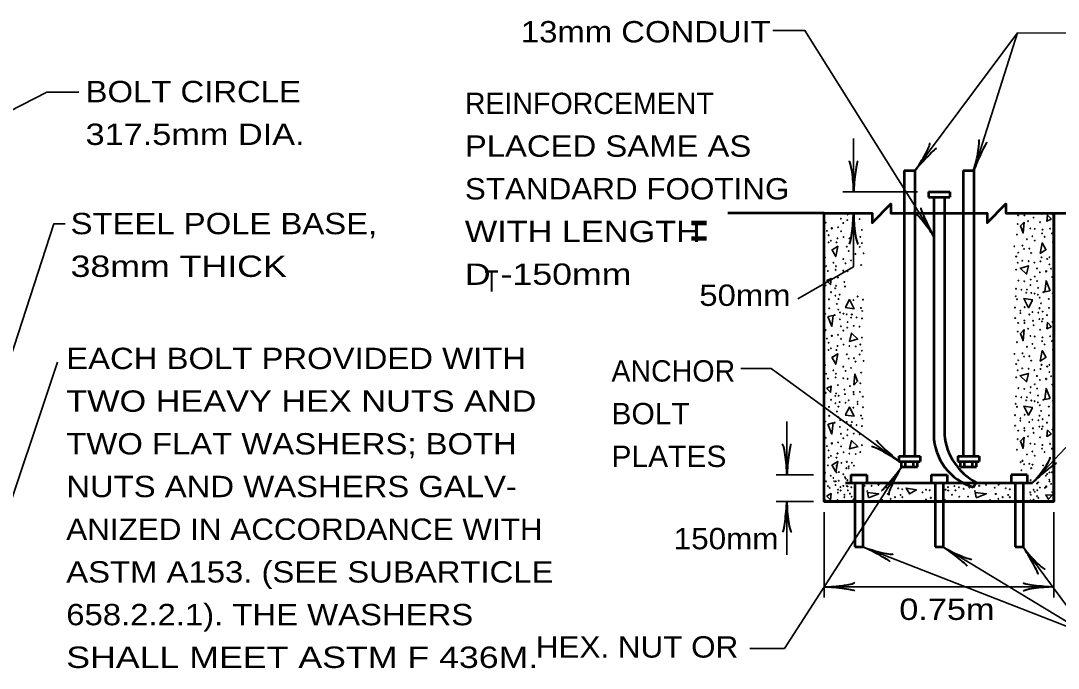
# Model space of a CAD drawing. Extents: x -35 to 821, y -13 to 531.
# Drawn here: x 339.2 to 455.8, y 171.6 to 244.4 of the extents above; entities that cross this region are included whole.
import ezdxf

# ---------------------------------------------------------------- set-up
doc = ezdxf.new("R2010")
doc.units = 0
doc.header["$LTSCALE"] = 0.96
doc.layers.add('1', color=7, linetype='Continuous', lineweight=53)

msp = doc.modelspace()

# ---------------------------------------------------------------- linework, layer by layer
at = {"layer": '1', "lineweight": 35}
for p, q in [((439.7334, 227.5357), (451.256, 243.0208)), ((342.1524, 236.3488), (311.1905, 220.4616)), ((342.1524, 236.3488), (345.7524, 236.3488)), ((432.8334, 225.1357), (432.8334, 231.1357)), ((440.0334, 225.1357), (431.6334, 225.1357)), ((432.8334, 222.7356), (432.8334, 216.7356)), ((432.8334, 216.7356), (426.5646, 213.1228)), ((333.7347, 177.2878), (343.3335, 205.9941)), ((425.3334, 193.3357), (425.3334, 199.3357)), ((438.2334, 194.2357), (425.0803, 173.8214)), ((428.3334, 193.3357), (424.1334, 193.3357)), ((428.3334, 190.3357), (424.1334, 190.3357)), ((425.3334, 190.3357), (425.3334, 184.3357)), ((429.5334, 189.1357), (429.5334, 179.5357)), ((455.3334, 189.1357), (455.3334, 179.5357)), ((433.8834, 185.2357), (459.1446, 175.3797)), ((442.8834, 185.2357), (459.1446, 175.3797)), ((451.8834, 185.2357), (459.1446, 175.3797)), ((429.5334, 180.7357), (455.3334, 180.7357)), ((425.0803, 173.8214), (421.1616, 173.8214))]:
    msp.add_line(p, q, dxfattribs=at)
at = {"layer": '1'}
for p, q in [((438.5334, 227.5357), (438.5334, 195.4357)), ((438.5334, 227.5357), (439.7334, 227.5357)), ((439.7334, 227.5357), (439.7334, 195.4357)), ((445.1334, 227.5357), (445.1334, 195.4357)), ((445.1334, 227.5357), (446.3334, 227.5357)), ((446.3334, 227.5357), (446.3334, 195.4357)), ((441.2334, 225.1357), (443.6334, 225.1357)), ((441.2334, 225.1357), (441.2334, 224.5357)), ((443.6334, 225.1357), (443.6334, 224.5357)), ((441.2334, 224.5357), (443.6334, 224.5357)), ((441.8334, 224.5357), (441.8334, 197.8357)), ((443.0334, 224.5357), (443.0334, 197.8357)), ((429.5334, 222.7356), (418.7121, 222.7356)), ((429.5334, 190.3357), (429.5334, 222.7356)), ((455.3334, 222.7358), (464.9547, 222.7358)), ((455.3334, 190.3357), (455.3334, 222.7358)), ((437.9334, 195.4357), (440.3334, 195.4357)), ((437.9334, 195.4357), (437.9334, 194.8357)), ((437.9334, 194.8357), (440.3334, 194.8357)), ((438.2334, 194.2357), (438.2334, 194.8357)), ((438.6834, 194.2357), (438.6834, 194.8357)), ((439.5834, 194.2357), (439.5834, 194.8357)), ((440.0334, 194.2357), (440.0334, 194.8357)), ((440.3334, 195.4357), (440.3334, 194.8357)), ((444.5334, 195.4357), (446.9334, 195.4357)), ((444.5334, 195.4357), (444.5334, 194.8357)), ((444.5334, 194.8357), (446.9334, 194.8357)), ((444.8334, 194.2357), (444.8334, 194.8357)), ((445.2834, 194.2357), (445.2834, 194.8357)), ((446.1834, 194.2357), (446.1834, 194.8357)), ((446.6334, 194.2357), (446.6334, 194.8357)), ((446.9334, 195.4357), (446.9334, 194.8357)), ((438.2334, 194.2357), (440.0334, 194.2357)), ((444.8334, 194.2357), (446.6334, 194.2357)), ((431.9334, 192.4357), (452.9334, 192.4357)), ((432.5334, 193.3357), (432.5334, 192.4357)), ((432.5334, 193.3357), (434.3334, 193.3357)), ((432.9834, 192.4357), (432.9834, 185.2357)), ((433.8834, 192.4357), (433.8834, 185.2357)), ((434.3334, 193.3357), (434.3334, 192.4357)), ((441.5334, 193.3357), (441.5334, 192.4357)), ((441.5334, 193.3357), (443.3334, 193.3357)), ((441.9834, 192.4357), (441.9834, 185.2357)), ((442.8834, 192.4357), (442.8834, 185.2357)), ((443.3334, 193.3357), (443.3334, 192.4357)), ((446.6076, 192.4697), (446.2673, 191.8959)), ((450.5334, 193.3357), (450.5334, 192.4357)), ((452.3334, 193.3357), (450.5334, 193.3357)), ((450.9834, 192.4357), (450.9834, 185.2357)), ((451.8834, 192.4357), (451.8834, 185.2357)), ((452.3334, 193.3357), (452.3334, 192.4357)), ((429.5334, 190.3357), (455.3334, 190.3357)), ((432.9834, 185.2357), (433.8834, 185.2357)), ((441.9834, 185.2357), (442.8834, 185.2357)), ((450.9834, 185.2357), (451.8834, 185.2357))]:
    msp.add_line(p, q, dxfattribs=at)
at = {"layer": '1', "lineweight": 35}
for points in [[(441.8334, 220.1625), (427.3681, 243.2875), (423.7562, 243.2875)], [(446.3334, 227.5357), (451.256, 243.0208), (456.9977, 243.0019)], [(455.0934, 222.0878), (454.6134, 222.5438), (454.5654, 221.8478), (455.0454, 222.0878)], [(326.909, 172.1878), (342.9245, 221.5527), (344.2093, 221.5527)], [(454.4694, 218.6078), (454.0374, 219.3998), (453.8214, 218.2238), (454.4934, 218.6558)], [(430.3974, 218.6557), (430.8294, 217.8637), (431.0454, 219.0397), (430.3734, 218.6077)], [(451.5174, 216.5438), (452.4774, 216.8318), (452.2854, 215.8958), (451.5654, 216.5678)], [(429.7734, 215.1757), (430.2534, 214.7197), (430.3014, 215.4157), (429.8214, 215.1757)], [(454.9254, 214.0238), (454.4694, 215.1518), (454.3254, 213.9038), (454.8774, 214.0238)], [(431.9094, 212.1997), (432.3894, 213.0397), (432.8934, 212.0077), (431.8854, 212.1517)], [(452.9574, 212.9678), (452.4774, 212.1278), (451.9734, 213.1598), (452.9814, 213.0158)], [(429.9414, 211.1437), (430.3974, 210.0157), (430.5414, 211.2637), (429.9894, 211.1437)], [(455.0934, 209.9918), (454.6134, 210.4478), (454.5654, 209.7518), (455.0454, 209.9918)], [(433.3494, 208.6237), (432.3894, 208.3357), (432.5814, 209.2717), (433.3014, 208.5997)], [(430.3974, 206.5597), (430.8294, 205.7677), (431.0454, 206.9437), (430.3734, 206.5117)], [(454.4694, 206.5118), (454.0374, 207.3038), (453.8214, 206.1278), (454.4934, 206.5598)], [(437.9334, 194.8357), (423.5538, 205.2899), (420.1719, 205.2899)], [(452.9334, 192.4357), (465.3716, 205.6121), (469.2367, 205.6121)], [(451.5174, 204.4478), (452.4774, 204.7358), (452.2854, 203.7998), (451.5654, 204.4718)], [(429.7734, 203.0797), (430.2534, 202.6237), (430.3014, 203.3197), (429.8214, 203.0797)], [(454.9254, 201.9278), (454.4694, 203.0558), (454.3254, 201.8078), (454.8774, 201.9278)], [(431.9094, 200.1037), (432.3894, 200.9437), (432.8934, 199.9117), (431.8854, 200.0557)], [(452.9574, 200.8718), (452.4774, 200.0318), (451.9734, 201.0638), (452.9814, 200.9198)], [(429.9414, 199.0477), (430.3974, 197.9197), (430.5414, 199.1677), (429.9894, 199.0477)], [(455.0934, 197.8958), (454.6134, 198.3518), (454.5654, 197.6558), (455.0454, 197.8958)], [(433.3494, 196.5277), (432.3894, 196.2397), (432.5814, 197.1757), (433.3014, 196.5037)], [(430.3974, 194.4637), (430.8294, 193.6717), (431.0454, 194.8477), (430.3734, 194.4157)], [(434.5254, 190.7437), (435.6534, 191.1997), (434.4054, 191.3437), (434.5254, 190.7917)], [(439.1094, 191.1997), (439.9014, 191.6317), (438.7254, 191.8477), (439.1574, 191.1757)], [(446.6214, 190.7437), (447.7494, 191.1997), (446.5014, 191.3437), (446.6214, 190.7917)], [(429.7734, 190.9837), (430.2534, 190.5277), (430.3014, 191.2237), (429.8214, 190.9837)], [(454.6854, 190.5757), (455.1414, 191.0557), (454.4454, 191.1037), (454.6854, 190.6237)]]:
    msp.add_lwpolyline(points, dxfattribs=at)
at = {"layer": '1'}
msp.add_lwpolyline([(429.5334, 222.7356), (434.9121, 222.7356), (434.9121, 221.675), (437.0334, 223.7963), (437.0334, 222.7357), (447.8334, 222.7357), (447.8334, 221.6751), (449.9547, 223.7964), (449.9547, 222.7358), (455.3334, 222.7358), (455.3334, 190.3357), (429.5334, 190.3357)], close=True, dxfattribs=at)
at = {"layer": '1', "lineweight": 35}
for points in [[(452.0214, 221.7518), (451.8774, 220.5038), (451.5894, 221.3198)], [(452.0214, 209.6558), (451.8774, 208.4078), (451.5894, 209.2238)], [(432.8454, 203.4157), (432.9894, 204.6637), (433.2774, 203.8477)], [(452.0214, 197.5598), (451.8774, 196.3118), (451.5894, 197.1278)]]:
    msp.add_lwpolyline(points, close=True, dxfattribs=at)
for centre in [(429.7048, 221.6917), (431.407, 222.1371), (431.6774, 221.6441), (432.1229, 221.978), (432.1547, 222.5982), (433.5069, 222.0894), (451.328, 222.5058), (452.044, 222.5058), (452.4416, 221.8537), (453.0621, 222.2514), (453.7939, 221.7424), (454.0007, 222.6807), (455.178, 222.6171), (429.832, 220.7535), (430.3888, 221.0874), (430.3888, 221.0238), (431.0888, 221.167), (431.4229, 220.7216), (433.7616, 220.8648), (451.2803, 221.5356), (452.7121, 221.0426), (453.1894, 220.9791), (454.0166, 220.47), (454.0643, 220.8836), (454.9234, 221.0108), (455.1302, 220.47), (430.0229, 220.2763), (430.0229, 219.4652), (430.2775, 219.6561), (430.9139, 219.4653), (431.0251, 219.9264), (431.7093, 220.0696), (432.3615, 219.9105), (433.5865, 220.0855), (433.7616, 219.3857), (451.1849, 220.3428), (452.3143, 219.8181), (452.9349, 220.152), (453.1894, 219.6749), (454.303, 220.0884), (455.2416, 219.4999), (429.5457, 218.7177), (432.0752, 218.9881), (432.282, 218.4951), (433.0456, 218.1611), (433.5229, 218.9563), (433.9524, 218.2407), (450.9144, 219.0228), (451.3439, 218.3072), (451.8212, 219.1024), (451.9962, 218.7206), (452.5848, 218.7684), (452.7916, 218.2754), (455.3211, 218.5458), (429.6252, 217.7636), (430.5638, 217.1751), (431.6774, 217.5886), (431.9319, 217.1115), (432.5525, 217.4454), (433.6819, 216.9207), (451.1052, 217.8778), (451.2803, 217.178), (451.7894, 217.4007), (452.5053, 217.353), (453.1575, 217.1939), (453.8417, 217.3371), (453.9529, 217.7982), (454.5893, 217.6074), (454.8439, 217.7983), (454.8439, 216.9872), (429.7366, 216.7935), (429.9434, 216.2527), (430.8025, 216.3799), (430.8502, 216.7935), (431.6774, 216.2844), (432.1547, 216.2209), (451.1052, 216.3987), (453.4439, 216.5419), (453.778, 216.0965), (454.478, 216.2397), (454.478, 216.1761), (455.0348, 216.51), (429.6888, 214.6464), (430.8661, 214.5828), (431.0729, 215.5211), (431.8047, 215.0121), (451.3599, 215.1741), (452.0121, 215.0947), (452.7121, 214.6653), (452.7439, 215.2855), (453.1894, 215.6194), (453.4598, 215.1264), (455.162, 215.5718), (429.4662, 213.6194), (430.2933, 213.8739), (430.7706, 214.3033), (430.7865, 213.4762), (431.2638, 213.6036), (431.8683, 214.51), (451.0576, 213.4088), (451.0894, 214.2517), (451.6939, 214.1404), (452.2348, 213.8064), (452.3143, 214.1563), (452.8076, 213.7905), (453.1735, 213.711), (453.5553, 213.5838), (453.5712, 214.3471), (454.1598, 213.8701), (455.2256, 213.7428), (455.2734, 214.5062), (429.5298, 213.0151), (430.0707, 213.0628), (430.9615, 212.5538), (431.1365, 213.0946), (432.807, 212.9832), (433.2843, 213.3809), (433.8888, 213.031), (451.2007, 213.0748), (453.762, 213.2498), (453.9053, 212.6137), (454.7802, 213.1067), (429.6412, 211.4247), (430.0866, 212.0608), (430.707, 211.2974), (431.1048, 211.9177), (431.3115, 211.5837), (431.6933, 211.4565), (432.0592, 211.377), (432.632, 211.3611), (433.6661, 212.0927), (433.8092, 211.7587), (450.978, 212.1365), (451.5825, 211.7866), (451.5825, 211.5163), (452.0598, 212.1843), (452.5848, 211.3572), (452.9349, 211.6277), (453.603, 211.5639), (453.7303, 212.0729), (454.0803, 211.6913), (454.5735, 211.2936), (454.7961, 212.1047), (455.337, 212.1524), (455.4006, 211.5481), (429.5934, 210.6613), (431.2956, 210.8204), (431.407, 210.0411), (432.1547, 210.5022), (432.5525, 211.0112), (432.8547, 210.0728), (433.1729, 211.0271), (433.5069, 209.9934), (433.7774, 210.9158), (450.994, 210.9597), (451.328, 210.4098), (452.0253, 210.6811), (452.044, 210.4098), (452.9985, 210.6575), (453.0621, 210.1554), (453.7144, 210.8484), (454.0007, 210.5847), (454.0962, 210.8642), (455.178, 210.5211), (429.7048, 209.5957), (430.3888, 208.9914), (430.3888, 208.9278), (431.0888, 209.071), (431.6774, 209.5481), (432.1229, 209.882), (433.7616, 208.7688), (451.2803, 209.4396), (452.4416, 209.7577), (452.7121, 208.9466), (453.1894, 208.8831), (453.7939, 209.6464), (454.0643, 208.7876), (454.9234, 208.9148), (429.832, 208.6575), (430.0229, 208.1803), (430.2775, 207.5601), (431.0251, 207.8304), (431.4229, 208.6256), (431.7093, 207.9736), (432.3615, 207.8145), (433.0774, 207.7668), (433.5865, 207.9895), (451.1849, 208.2468), (452.3143, 207.7221), (452.9349, 208.056), (453.1894, 207.5789), (454.0166, 208.374), (454.303, 207.9924), (455.1302, 208.374), (429.5457, 206.6217), (430.0229, 207.3692), (430.9139, 207.3693), (432.0752, 206.8921), (432.282, 206.3991), (432.8706, 206.4469), (433.5229, 206.8603), (433.7616, 207.2897), (450.9144, 206.9268), (451.8212, 207.0064), (451.9962, 206.6246), (452.5848, 206.6724), (455.2416, 207.4039), (455.3211, 206.4498), (429.6252, 205.6676), (431.6774, 205.4926), (432.5525, 205.3494), (433.0456, 206.0651), (433.9524, 206.1447), (451.1052, 205.7818), (451.3439, 206.2112), (451.7894, 205.3047), (452.5053, 205.257), (452.7916, 206.1794), (453.8417, 205.2411), (453.9529, 205.7022), (454.5893, 205.5114), (454.8439, 205.7023), (429.7366, 204.6975), (429.9434, 204.1567), (430.5638, 205.0791), (430.8025, 204.2839), (430.8502, 204.6975), (431.6774, 204.1884), (431.9319, 205.0155), (432.1547, 204.1249), (433.6819, 204.8247), (451.1052, 204.3027), (451.2803, 205.082), (453.1575, 205.0979), (453.4439, 204.4459), (454.478, 204.1437), (454.478, 204.0801), (454.8439, 204.8912), (455.0348, 204.414), (431.0729, 203.4251), (431.8047, 202.9161), (432.4252, 203.3138), (433.5865, 203.6319), (451.3599, 203.0781), (452.0121, 202.9987), (452.7439, 203.1895), (453.1894, 203.5234), (453.4598, 203.0304), (453.778, 204.0005), (455.162, 203.4758), (429.6888, 202.5504), (430.2933, 201.7779), (430.7706, 202.2073), (430.8661, 202.4868), (431.1524, 202.2231), (431.8683, 202.414), (432.8228, 202.6617), (432.8415, 202.3904), (433.5388, 202.6617), (433.8728, 202.1118), (451.0894, 202.1557), (451.6939, 202.0444), (452.3143, 202.0603), (452.7121, 202.5693), (453.5712, 202.2511), (454.1598, 201.7741), (455.2734, 202.4102), (429.4662, 201.5234), (429.5298, 200.9191), (430.0707, 200.9668), (430.7865, 201.3802), (431.1365, 200.9986), (431.2638, 201.5076), (431.9319, 201.4438), (432.282, 201.7143), (432.807, 200.8872), (433.2843, 201.5552), (433.2843, 201.2849), (433.8888, 200.935), (451.0576, 201.3128), (451.2007, 200.9788), (452.2348, 201.7104), (452.8076, 201.6945), (453.1735, 201.615), (453.5553, 201.4878), (453.762, 201.1538), (454.7802, 201.0107), (455.2256, 201.6468), (430.0866, 199.9648), (430.9615, 200.4578), (431.1048, 199.8217), (431.3115, 199.4877), (433.6661, 199.9967), (433.8092, 199.6627), (450.978, 200.0405), (451.5825, 199.6906), (451.5825, 199.4203), (452.0598, 200.0883), (452.9349, 199.5317), (453.603, 199.4679), (453.7303, 199.9769), (453.9053, 200.5177), (454.0803, 199.5953), (454.7961, 200.0087), (455.337, 200.0564), (455.4006, 199.4521), (429.5934, 198.5653), (429.6412, 199.3287), (430.707, 199.2014), (431.2956, 198.7244), (431.6933, 199.3605), (432.0592, 199.281), (432.1547, 198.4062), (432.5525, 198.9152), (432.632, 199.2651), (433.1729, 198.9311), (433.7774, 198.8198), (450.994, 198.8637), (451.328, 198.3138), (452.0253, 198.5851), (452.044, 198.3138), (452.5848, 199.2612), (452.9985, 198.5615), (453.7144, 198.7524), (454.0007, 198.4887), (454.0962, 198.7682), (454.5735, 199.1976), (455.178, 198.4251), (429.7048, 197.4997), (431.407, 197.9451), (431.6774, 197.4521), (432.1229, 197.786), (432.8547, 197.9768), (433.5069, 197.8974), (451.2803, 197.3436), (452.4416, 197.6617), (453.0621, 198.0594), (453.7939, 197.5504), (429.832, 196.5615), (430.0229, 196.0843), (430.3888, 196.8954), (430.3888, 196.8318), (431.0888, 196.975), (431.4229, 196.5296), (433.5865, 195.8935), (433.7616, 196.6728), (451.1849, 196.1508), (452.7121, 196.8506), (452.9349, 195.96), (453.1894, 196.7871), (454.0166, 196.278), (454.0643, 196.6916), (454.303, 195.8964), (454.9234, 196.8188), (455.1302, 196.278), (430.0229, 195.2732), (430.2775, 195.4641), (430.9139, 195.2733), (431.0251, 195.7344), (431.7093, 195.8776), (432.0752, 194.7961), (432.3615, 195.7185), (433.0774, 195.6708), (451.6204, 194.7547), (451.8212, 194.9104), (452.3143, 195.6261), (453.1894, 195.4829), (429.5457, 194.5257), (429.6252, 193.5716), (429.9412, 194.3888), (430.9114, 194.3411), (430.9114, 193.6251), (431.1827, 193.6438), (431.4613, 194.6751), (432.0179, 194.0866), (432.282, 194.3031), (432.2882, 194.0866), (432.6381, 194.6911), (432.8706, 194.3509), (443.0074, 194.3411), (451.7, 193.8479), (451.9962, 194.5286), (452.5848, 194.5764), (452.7916, 194.0834), (452.9404, 194.4842), (454.1332, 194.3888), (454.8439, 193.6063), (455.1034, 193.6251), (429.7366, 192.6015), (430.2593, 193.2275), (430.5638, 192.9831), (430.657, 192.607), (430.8502, 192.6015), (431.1591, 192.6706), (431.6774, 193.3966), (431.8588, 193.0843), (431.9319, 192.9195), (432.1293, 192.7342), (452.7496, 192.7342), (453.5767, 192.4797), (454.4513, 193.2275), (454.5893, 193.4154), (454.8439, 192.7952), (454.849, 192.607), (429.9434, 192.0607), (430.148, 191.8752), (430.8025, 192.1879), (431.0729, 191.3291), (431.0863, 191.6684), (431.35, 191.9547), (431.3658, 191.5729), (431.6774, 192.0924), (432.0655, 192.0661), (432.1547, 192.0289), (432.1929, 191.5888), (432.5745, 191.9388), (434.0854, 192.1138), (434.3717, 191.5093), (434.8487, 192.0979), (435.628, 192.2093), (436.5981, 191.8911), (437.0435, 192.2252), (437.8387, 191.8274), (438.2998, 191.7162), (440.59, 191.3661), (440.9716, 191.6525), (441.3852, 191.6048), (443.1823, 191.6684), (443.446, 191.9547), (443.4618, 191.5729), (444.1615, 192.0661), (444.2889, 191.5888), (444.6705, 191.9388), (445.2113, 191.7638), (445.8474, 191.9071), (446.4677, 191.5093), (446.9447, 192.0979), (447.724, 192.2093), (448.6941, 191.8911), (449.1395, 192.2252), (449.9347, 191.8274), (450.3958, 191.7162), (452.686, 191.3661), (453.0676, 191.6525), (453.1894, 191.4274), (453.4439, 192.3499), (453.4812, 191.6048), (453.778, 191.9045), (454.34, 191.8752), (454.478, 192.0477), (454.478, 191.9841), (455.0348, 192.318), (455.162, 191.3798), (455.2783, 191.6684), (429.6888, 190.4544), (430.8661, 190.3908), (431.0227, 190.4911), (431.7952, 191.0956), (431.8047, 190.8201), (432.4252, 191.2178), (432.6063, 190.873), (432.8228, 190.5657), (436.0734, 190.5071), (436.6777, 191.1911), (436.7413, 191.1911), (437.0116, 190.6343), (437.4888, 190.8252), (438.109, 191.0798), (438.2999, 190.8252), (440.9716, 190.5389), (441.5124, 190.7457), (443.1187, 190.4911), (443.8912, 191.0956), (444.7023, 190.873), (445.7043, 190.8889), (448.1694, 190.5071), (448.7737, 191.1911), (448.8373, 191.1911), (449.1076, 190.6343), (449.5848, 190.8252), (450.205, 191.0798), (450.3959, 190.8252), (452.7121, 190.4733), (452.7439, 191.0935), (453.0676, 190.5389), (453.4598, 190.9344), (453.6084, 190.7457)]:
    msp.add_circle(centre, 0.0318, dxfattribs=at)
at = {"layer": '1'}
for centre, radius, start, end in [((448.1288, 197.9708), 6.2969, 181.22976, 252.89151), ((449.8331, 198.4914), 6.8312, 185.50839, 241.8245)]:
    msp.add_arc(centre, radius, start, end, dxfattribs=at)
at = {"layer": '1', "lineweight": 40}
for centre, major_axis, ratio, start_param, end_param in [((446.4141, 228.8841), (-0.4706, -2.0989), 0.122415, 0.89635335, 3.14159265), ((440.2491, 228.7841), (-1.1289, -1.831), 0.122415, 0.89635335, 3.14159265), ((440.7398, 228.4628), (1.4274, 1.5651), 0.07063, 6.28230741, 8.55970261), ((446.9827, 228.7402), (0.8394, 1.9448), 0.07063, 6.28230741, 8.55970261), ((432.5018, 226.4451), (0.1874, -2.1428), 0.122415, 0.89635335, 3.14159265), ((432.5018, 226.4451), (0.1874, -2.1428), 0.122415, 0.89635335, 3.14159265), ((433.0873, 226.4803), (-0.2108, -2.1077), 0.07063, 3.14071475, 5.41810995), ((433.0873, 226.4803), (-0.2108, -2.1077), 0.07063, 3.14071475, 5.41810995), ((432.5795, 221.391), (0.2108, 2.1077), 0.07063, 3.14071475, 5.41810995), ((433.165, 221.4262), (-0.1874, 2.1428), 0.122415, 0.89635335, 3.14159265), ((440.8579, 221.0968), (1.2953, -1.7173), 0.122415, 0.89635335, 3.14159265), ((441.3356, 221.4371), (0.9391, -1.8987), 0.07063, 3.14071475, 5.41810995), ((436.9952, 195.8318), (-1.5809, 1.4099), 0.07063, 6.28230741, 8.55970261), ((425.0018, 194.6451), (0.1874, -2.1428), 0.122415, 0.89635335, 3.14159265), ((425.5873, 194.6803), (-0.2108, -2.1077), 0.07063, 3.14071475, 5.41810995), ((436.6793, 195.3375), (1.8434, -1.1085), 0.122415, 0.89635335, 3.14159265), ((453.5912, 193.6155), (-1.3347, -1.6869), 0.122415, 0.89635335, 3.14159265), ((437.2917, 193.2429), (1.3188, 1.6577), 0.07063, 3.14071475, 5.41810995), ((437.8029, 192.9554), (1.0031, 1.9028), 0.122415, 0.89635335, 3.14159265), ((454.041, 193.2392), (1.6001, 1.388), 0.07063, 6.28230741, 8.55970261), ((425.0795, 188.9911), (0.2108, 2.1077), 0.07063, 3.14071475, 5.41810995), ((425.665, 189.0263), (-0.1874, 2.1428), 0.122415, 0.89635335, 3.14159265), ((435.0437, 184.5104), (1.887, -0.9625), 0.07063, 6.28230741, 8.55970261), ((435.0437, 184.5104), (1.887, -0.9625), 0.07063, 6.28230741, 8.55970261), ((435.2238, 185.0686), (-2.0644, 0.6043), 0.122415, 0.89635335, 3.14159265), ((435.2238, 185.0686), (-2.0644, 0.6043), 0.122415, 0.89635335, 3.14159265), ((443.9017, 184.3216), (-1.6932, 1.2728), 0.07063, 3.14071475, 5.41810995), ((443.9017, 184.3216), (-1.6932, 1.2728), 0.07063, 3.14071475, 5.41810995), ((444.1751, 184.8405), (-1.9296, 0.9505), 0.122415, 0.89635335, 3.14159265), ((444.1751, 184.8405), (-1.9296, 0.9505), 0.122415, 0.89635335, 3.14159265), ((452.4765, 184.0026), (-1.0805, 1.822), 0.07063, 3.14071475, 5.41810995), ((452.927, 184.3781), (-1.4219, 1.6141), 0.122415, 0.89635335, 3.14159265), ((430.8428, 181.0673), (-2.1428, -0.1874), 0.122415, 0.89635335, 3.14159265), ((430.8428, 181.0673), (-2.1428, -0.1874), 0.122415, 0.89635335, 3.14159265), ((453.9888, 180.9896), (2.1077, -0.2108), 0.07063, 3.14071475, 5.41810995), ((430.878, 180.4818), (-2.1077, 0.2108), 0.07063, 3.14071475, 5.41810995), ((430.878, 180.4818), (-2.1077, 0.2108), 0.07063, 3.14071475, 5.41810995), ((454.024, 180.4041), (2.1428, 0.1874), 0.122415, 0.89635335, 3.14159265)]:
    msp.add_ellipse(centre, major_axis=major_axis, ratio=ratio, start_param=start_param, end_param=end_param, dxfattribs=at)

# ---------------------------------------------------------------- texts
at = {"layer": '1'}
for s, height, width, p in [('13mm CONDUIT', 2.4, 1.15, (395.4335, 241.9489)), ('BOLT CIRCLE', 2.4, 1.15, (346.5056, 235.2218)), ('317.5mm DIA.', 2.4, 1.2, (346.5056, 230.4218)), ('PLACED SAME AS', 2.4, 1.15, (389.1359, 229.0927)), ('STANDARD FOOTING', 2.4, 1.1, (389.1359, 224.2927)), ('STEEL POLE BASE,', 2.4, 1.15, (344.8175, 220.3861)), ('WITH LENGTH  ', 2.4, 1.2, (389.1359, 219.4927)), ('=', 4.8, 0.55, (414.4211, 218.4812)), ('38mm THICK', 2.4, 1.25, (344.8175, 215.5861)), ('D -150mm', 2.4, 1.25, (389.1359, 214.6927)), ('T', 2.4, 0.8, (391.3561, 213.9352)), ('50mm', 2.4, 1.15, (415.491, 212.3257)), ('EACH BOLT PROVIDED WITH', 2.4, 1.15, (344.3317, 205.2232)), ('TWO HEAVY HEX NUTS AND', 2.4, 1.2, (344.3317, 200.4232)), ('BOLT', 2.4, 1.05, (405.6142, 199.0166)), ('TWO FLAT WASHERS; BOTH', 2.4, 1.15, (344.3317, 195.6232)), ('PLATES', 2.4, 1.05, (405.6142, 194.2166)), ('NUTS AND WASHERS GALV-', 2.4, 1.15, (344.3317, 190.8232)), ('ANIZED IN ACCORDANCE WITH', 2.4, 1.1, (344.3317, 186.0232)), ('150mm', 2.4, 1.1, (412.6138, 184.966)), ('ASTM A153. (SEE SUBARTICLE', 2.4, 1.15, (344.3317, 181.2232)), ('658.2.2.1). THE WASHERS', 2.4, 1.15, (344.3317, 176.4232)), ('0.75m', 2.4, 1.2, (437.9691, 177.0217)), ('HEX. NUT OR', 2.4, 1.1, (397.1149, 172.7871)), ('SHALL MEET ASTM F 436M.', 2.4, 1.25, (344.3317, 171.6232))]:
    msp.add_text(s, height=height, dxfattribs=dict(at, width=width)).set_placement(p)
for s, p in [('REINFORCEMENT', (389.1359, 233.8927)), ('ANCHOR', (405.6142, 203.8166))]:
    msp.add_text(s, height=2.4, dxfattribs=at).set_placement(p)

doc.saveas('drawing.dxf')
